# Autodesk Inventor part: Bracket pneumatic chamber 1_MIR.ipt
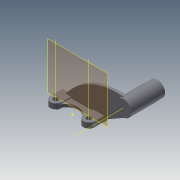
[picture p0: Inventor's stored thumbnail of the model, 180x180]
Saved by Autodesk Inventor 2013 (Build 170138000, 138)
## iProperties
Created: 2005-03
Part Number: Bracket pneumatic chamber 1_MIR.ipt
Material: Steel, Mild
Document SubType Name: Modeling
Designer: salex
Manufacturer: Standard
Standards Organization: Custom
Density: 7.86 g/cm^3
Mass: 4464.91 g
Surface Area: 799.794 cm^2
Volume: 568.055 cm^3
Author: salex
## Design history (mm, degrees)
derived "Bracket pneumatic chamber 1.ipt"
  node "WorkPlane1"
  node "WorkPlane2"
  node "WorkPlane3"
  node "РабОсь3"
  node "РабОсь4"
  node "WorkAxis1"
  node "WorkAxis2"
body "Solid1"
tag "TaggingFeature2"
node "РабПлоскость12"
node "РабПлоскость13"
node "РабПлоскость3"
node "РабОсь11"
node "РабОсь12"
node "РабОсь13"
node "РабОсь14"
node "РабОсь8"
node "РабТочка2"
feature "DerivedBody::Bracket pneumatic chamber 1.ipt"
